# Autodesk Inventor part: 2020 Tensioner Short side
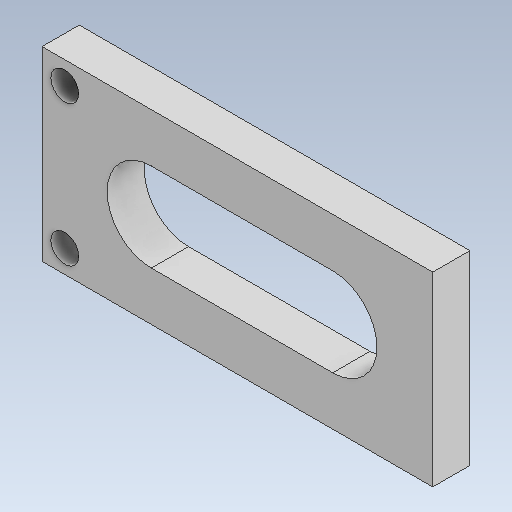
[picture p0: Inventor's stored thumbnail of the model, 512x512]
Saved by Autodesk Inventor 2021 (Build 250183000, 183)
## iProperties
Created: 2023-10
Part Number: 2020 Tensioner Short side
Material: Generico
Document SubType Name: Modeling
Designer: hp
Density: 1 g/cm^3
Appearance: Default
Author: hp
Revision Number: ANY
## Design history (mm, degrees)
feature "Solido1"
body "Solid1"
